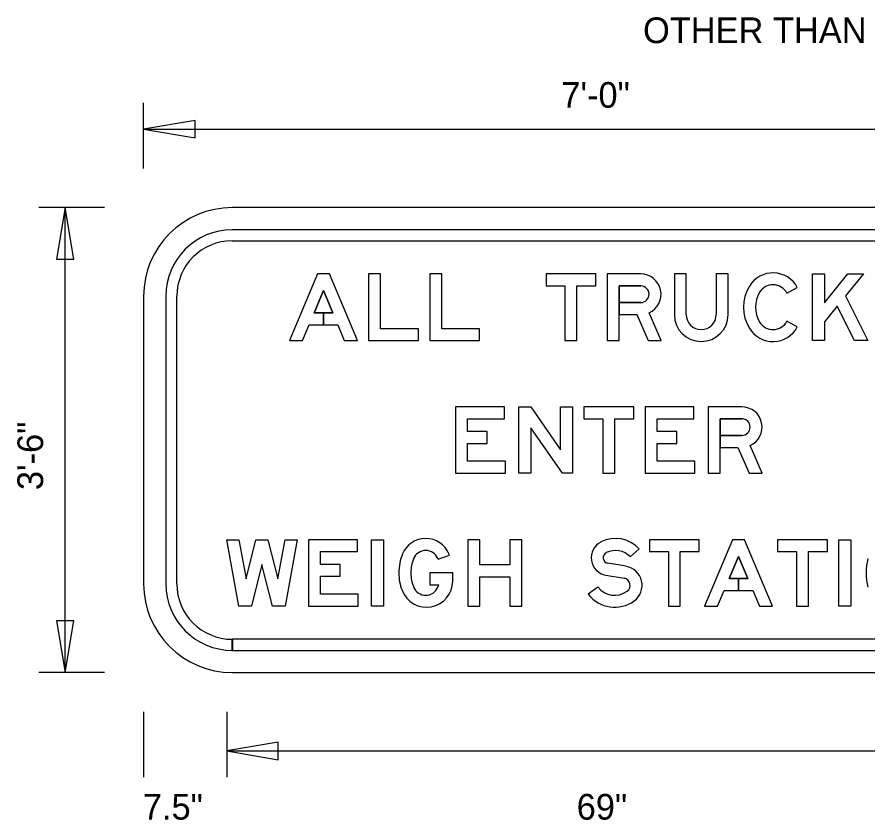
# Model space of a CAD drawing. Extents: x 0 to 770, y 0 to 495.
# Drawn here: x 203.8 to 319.6, y 378.3 to 487.7 of the extents above; entities that cross this region are included whole.
import ezdxf

# ---------------------------------------------------------------- set-up
doc = ezdxf.new("R2010")
doc.units = 0
for name, color, linetype in [('Dimension', 7, 'Continuous'), ('GSBWFill', 7, 'Continuous'), ('GSColorFill', 7, 'Continuous'), ('GSDims', 7, 'Continuous'), ('GSOutline', 7, 'Continuous'), ('TextStructures', 7, 'Continuous')]:
    doc.layers.add(name, color=color, linetype=linetype)

msp = doc.modelspace()

# ---------------------------------------------------------------- linework, layer by layer
at = {"layer": 'Dimension'}
for points in [[(221, 472.41), (228.02, 471.22), (228.02, 473.59)], [(210.32, 461.72), (209.13, 454.7), (211.5, 454.7)], [(210.32, 398.41), (211.5, 405.43), (209.13, 405.43)], [(232.31, 387.73), (239.32, 386.54), (239.32, 388.91)]]:
    msp.add_lwpolyline(points, close=True, dxfattribs=at)
at = {"layer": 'GSBWFill'}
for p, q in [((335.56, 461.72), (233.06, 461.72)), ((335.56, 458.71), (233.06, 458.71)), ((233.06, 457.2), (335.56, 457.2)), ((298.92, 452.68), (298.92, 447.14)), ((308.52, 450.08), (309.95, 450.85)), ((221, 449.66), (221, 410.47)), ((224.01, 449.66), (224.01, 410.47)), ((225.52, 410.47), (225.52, 449.66)), ((309.95, 445.46), (308.52, 446.23)), ((308.52, 446.23), (308.52, 446.23)), ((287.23, 414.15), (288.43, 415.25)), ((261.07, 413.85), (262.61, 414.4)), ((286.65, 412.87), (284.18, 413.29)), ((263.06, 410.86), (263.06, 411.98)), ((283.91, 411.68), (286.38, 411.26)), ((282.8, 410.05), (281.51, 409.06)), ((233.06, 401.42), (233.06, 402.93)), ((335.56, 402.93), (233.07, 402.93)), ((233.07, 402.93), (233.07, 401.42)), ((233.07, 401.42), (335.56, 401.42)), ((233.06, 398.41), (335.56, 398.41))]:
    msp.add_line(p, q, dxfattribs=at)
for points in [[(246.74, 447.39), (245.47, 447.39), (245.47, 445.76), (247.42, 445.76), (248.31, 443.63), (250.08, 443.63), (246.28, 452.68), (244.65, 452.68), (240.85, 443.63), (242.62, 443.63), (243.51, 445.76), (245.47, 445.76), (245.47, 447.39), (244.19, 447.39), (245.47, 450.41)], [(258.4, 443.63), (258.4, 445.21), (253.24, 445.21), (253.24, 452.68), (251.62, 452.68), (251.62, 443.63)], [(266.72, 443.63), (266.72, 445.21), (261.56, 445.21), (261.56, 452.68), (259.94, 452.68), (259.94, 443.63)], [(275.76, 451.05), (278.34, 451.05), (278.34, 443.63), (279.97, 443.63), (279.97, 451.05), (282.55, 451.05), (282.55, 452.68), (275.76, 452.68)], [(318.95, 452.68), (316.53, 449.69), (319.54, 443.63), (317.72, 443.63), (315.4, 448.3), (313.66, 446.16), (313.66, 443.63), (312.03, 443.63), (312.03, 452.68), (313.66, 452.68), (313.66, 448.75), (316.85, 452.68)], [(270.25, 427.17), (265.09, 427.17), (265.09, 429.6), (267.76, 429.6), (267.76, 431.23), (265.09, 431.23), (265.09, 432.96), (270.11, 432.96), (270.11, 434.59), (263.46, 434.59), (263.46, 425.54), (270.25, 425.54)], [(279.38, 434.59), (279.38, 425.54), (277.98, 425.54), (273.68, 431.74), (273.68, 425.54), (272.06, 425.54), (272.06, 434.59), (273.69, 434.59), (277.75, 428.73), (277.75, 434.59)], [(280.92, 432.96), (283.5, 432.96), (283.5, 425.54), (285.13, 425.54), (285.13, 432.96), (287.7, 432.96), (287.7, 434.59), (280.92, 434.59)], [(296.02, 427.17), (290.87, 427.17), (290.87, 429.6), (293.54, 429.6), (293.54, 431.23), (290.87, 431.23), (290.87, 432.96), (295.89, 432.96), (295.89, 434.59), (289.24, 434.59), (289.24, 425.54), (296.02, 425.54)], [(237.1, 413.11), (235.67, 407.45), (233.96, 407.45), (232.31, 416.5), (233.96, 416.5), (234.93, 411.17), (236.27, 416.5), (237.92, 416.5), (239.27, 411.17), (240.24, 416.5), (241.89, 416.5), (240.24, 407.45), (238.52, 407.45)], [(250.21, 409.08), (245.06, 409.08), (245.06, 411.51), (247.73, 411.51), (247.73, 413.14), (245.06, 413.14), (245.06, 414.87), (250.08, 414.87), (250.08, 416.5), (243.43, 416.5), (243.43, 407.45), (250.21, 407.45)], [(252.02, 407.45), (252.02, 416.5), (253.65, 416.5), (253.65, 407.45)], [(270.84, 413.06), (266.77, 413.06), (266.77, 416.5), (265.14, 416.5), (265.14, 407.45), (266.77, 407.45), (266.77, 411.43), (270.84, 411.43), (270.84, 407.45), (272.46, 407.45), (272.46, 416.5), (270.84, 416.5)], [(289.83, 414.87), (292.41, 414.87), (292.41, 407.45), (294.03, 407.45), (294.03, 414.87), (296.61, 414.87), (296.61, 416.5), (289.83, 416.5)], [(303.22, 411.21), (301.95, 411.21), (301.95, 409.58), (303.9, 409.58), (304.8, 407.45), (306.56, 407.45), (302.76, 416.5), (301.13, 416.5), (297.34, 407.45), (299.1, 407.45), (299.99, 409.58), (301.95, 409.58), (301.95, 411.21), (300.68, 411.21), (301.95, 414.23)], [(307.28, 414.87), (309.86, 414.87), (309.86, 407.45), (311.49, 407.45), (311.49, 414.87), (314.07, 414.87), (314.07, 416.5), (307.28, 416.5)], [(315.61, 407.45), (315.61, 416.5), (317.23, 416.5), (317.23, 407.45)]]:
    msp.add_lwpolyline(points, close=True, dxfattribs=at)
for points in [[(288.65, 452.68), (284.09, 452.68), (284.09, 443.63), (285.71, 443.63), (285.71, 451.05), (288.65, 451.05)], [(294.85, 447.14), (294.85, 452.68), (293.22, 452.68), (293.22, 447.14)], [(300.55, 447.14), (300.55, 452.68), (298.92, 452.68)], [(288.65, 448.79), (285.71, 448.79), (285.71, 447.16)], [(285.71, 447.16), (288.11, 447.16), (289.64, 443.63), (291.41, 443.63), (289.78, 447.4)], [(302.4, 434.59), (297.83, 434.59), (297.83, 425.54), (299.46, 425.54), (299.46, 432.96), (302.4, 432.96)], [(302.4, 430.7), (299.46, 430.7), (299.46, 429.07)], [(299.46, 429.07), (301.86, 429.07), (303.39, 425.54), (305.16, 425.54), (303.53, 429.31)], [(263.06, 411.98), (259.94, 411.98), (259.94, 410.35), (261.16, 410.35)]]:
    msp.add_lwpolyline(points, dxfattribs=at)
for centre, radius, start, end in [((233.06, 449.66), 12.06, 90, 180), ((233.06, 449.66), 9.04, 90, 180), ((233.06, 449.66), 7.54, 90, 180), ((296.88, 447.14), 3.66, 180, 0), ((296.88, 447.14), 2.04, 180, 0), ((259.39, 413.25), 3.41, 22.4256, 157.5744), ((284.31, 414.04), 2.4, 116.9123, 260.4087), ((285.21, 412.27), 4.39, 42.8759, 116.9123), ((259.39, 413.25), 1.78, 22.4256, 157.5744), ((284.31, 414.04), 0.769, 116.9123, 260.4087), ((285.21, 412.27), 2.76, 42.8759, 116.9123), ((262.47, 411.98), 6.74, 157.5744, 180), ((262.47, 411.98), 5.11, 157.5744, 180), ((256.32, 411.98), 5.11, 21.4721, 22.4256), ((256.32, 411.98), 6.74, 21.0425, 22.4256), ((286.21, 410.28), 2.62, 306.123, 80.4087), ((262.47, 411.98), 6.74, 180, 200.6303), ((262.47, 411.98), 5.11, 180, 202.4256), ((286.21, 410.28), 0.995, 306.123, 80.4087), ((233.06, 410.47), 12.06, 180, 270), ((233.06, 410.47), 9.04, 180, 270), ((233.06, 410.47), 7.54, 180, 270), ((259.5, 410.86), 3.56, 200.6303, 0), ((259.39, 410.71), 1.78, 202.4256, 337.5744), ((256.32, 411.98), 5.11, 337.5744, 341.4227), ((285.09, 411.82), 2.89, 217.5895, 306.123), ((285.09, 411.82), 4.52, 217.5895, 306.123)]:
    msp.add_arc(centre, radius, start, end, dxfattribs=at)
for centre, major_axis, start_param, end_param in [((306.64, 449.08), (0, 3.75), 5.201543, 7.308565), ((288.65, 449.92), (0, 2.76), 3.562504, 6.283185), ((288.65, 449.92), (0, 1.13), 3.141593, 6.283185), ((308.17, 448.15), (0, 5.54), 1.025379, 2.116213), ((306.64, 449.08), (0, 2.13), 5.201543, 7.308565), ((308.17, 448.15), (0, 3.91), 1.025379, 2.116213), ((306.64, 447.23), (0, 2.13), 2.116213, 4.223235), ((306.64, 447.23), (0, 3.75), 2.116213, 4.223235), ((302.4, 431.83), (0, 2.76), 3.562504, 6.283185), ((302.4, 431.83), (0, 1.13), 3.141593, 6.283185), ((326.91, 411.98), (0, 7.6), 1.309664, 1.831929)]:
    msp.add_ellipse(centre, major_axis=major_axis, ratio=0.999994, start_param=start_param, end_param=end_param, dxfattribs=at)
at = {"layer": 'GSColorFill'}
for p, q in [((298.92, 452.68), (298.92, 447.14)), ((308.52, 450.08), (309.95, 450.85)), ((309.95, 445.46), (308.52, 446.23)), ((308.52, 446.23), (308.52, 446.23)), ((287.23, 414.15), (288.43, 415.25)), ((261.07, 413.85), (262.61, 414.4)), ((286.65, 412.87), (284.18, 413.29)), ((263.06, 410.86), (263.06, 411.98)), ((283.91, 411.68), (286.38, 411.26)), ((282.8, 410.05), (281.51, 409.06))]:
    msp.add_line(p, q, dxfattribs=at)
for points in [[(246.74, 447.39), (245.47, 447.39), (245.47, 445.76), (247.42, 445.76), (248.31, 443.63), (250.08, 443.63), (246.28, 452.68), (244.65, 452.68), (240.85, 443.63), (242.62, 443.63), (243.51, 445.76), (245.47, 445.76), (245.47, 447.39), (244.19, 447.39), (245.47, 450.41)], [(258.4, 443.63), (258.4, 445.21), (253.24, 445.21), (253.24, 452.68), (251.62, 452.68), (251.62, 443.63)], [(266.72, 443.63), (266.72, 445.21), (261.56, 445.21), (261.56, 452.68), (259.94, 452.68), (259.94, 443.63)], [(275.76, 451.05), (278.34, 451.05), (278.34, 443.63), (279.97, 443.63), (279.97, 451.05), (282.55, 451.05), (282.55, 452.68), (275.76, 452.68)], [(318.95, 452.68), (316.53, 449.69), (319.54, 443.63), (317.72, 443.63), (315.4, 448.3), (313.66, 446.16), (313.66, 443.63), (312.03, 443.63), (312.03, 452.68), (313.66, 452.68), (313.66, 448.75), (316.85, 452.68)], [(270.25, 427.17), (265.09, 427.17), (265.09, 429.6), (267.76, 429.6), (267.76, 431.23), (265.09, 431.23), (265.09, 432.96), (270.11, 432.96), (270.11, 434.59), (263.46, 434.59), (263.46, 425.54), (270.25, 425.54)], [(279.38, 434.59), (279.38, 425.54), (277.98, 425.54), (273.68, 431.74), (273.68, 425.54), (272.06, 425.54), (272.06, 434.59), (273.69, 434.59), (277.75, 428.73), (277.75, 434.59)], [(280.92, 432.96), (283.5, 432.96), (283.5, 425.54), (285.13, 425.54), (285.13, 432.96), (287.7, 432.96), (287.7, 434.59), (280.92, 434.59)], [(296.02, 427.17), (290.87, 427.17), (290.87, 429.6), (293.54, 429.6), (293.54, 431.23), (290.87, 431.23), (290.87, 432.96), (295.89, 432.96), (295.89, 434.59), (289.24, 434.59), (289.24, 425.54), (296.02, 425.54)], [(237.1, 413.11), (235.67, 407.45), (233.96, 407.45), (232.31, 416.5), (233.96, 416.5), (234.93, 411.17), (236.27, 416.5), (237.92, 416.5), (239.27, 411.17), (240.24, 416.5), (241.89, 416.5), (240.24, 407.45), (238.52, 407.45)], [(250.21, 409.08), (245.06, 409.08), (245.06, 411.51), (247.73, 411.51), (247.73, 413.14), (245.06, 413.14), (245.06, 414.87), (250.08, 414.87), (250.08, 416.5), (243.43, 416.5), (243.43, 407.45), (250.21, 407.45)], [(252.02, 407.45), (252.02, 416.5), (253.65, 416.5), (253.65, 407.45)], [(270.84, 413.06), (266.77, 413.06), (266.77, 416.5), (265.14, 416.5), (265.14, 407.45), (266.77, 407.45), (266.77, 411.43), (270.84, 411.43), (270.84, 407.45), (272.46, 407.45), (272.46, 416.5), (270.84, 416.5)], [(289.83, 414.87), (292.41, 414.87), (292.41, 407.45), (294.03, 407.45), (294.03, 414.87), (296.61, 414.87), (296.61, 416.5), (289.83, 416.5)], [(303.22, 411.21), (301.95, 411.21), (301.95, 409.58), (303.9, 409.58), (304.8, 407.45), (306.56, 407.45), (302.76, 416.5), (301.13, 416.5), (297.34, 407.45), (299.1, 407.45), (299.99, 409.58), (301.95, 409.58), (301.95, 411.21), (300.68, 411.21), (301.95, 414.23)], [(307.28, 414.87), (309.86, 414.87), (309.86, 407.45), (311.49, 407.45), (311.49, 414.87), (314.07, 414.87), (314.07, 416.5), (307.28, 416.5)], [(315.61, 407.45), (315.61, 416.5), (317.23, 416.5), (317.23, 407.45)]]:
    msp.add_lwpolyline(points, close=True, dxfattribs=at)
for points in [[(288.65, 452.68), (284.09, 452.68), (284.09, 443.63), (285.71, 443.63), (285.71, 451.05), (288.65, 451.05)], [(294.85, 447.14), (294.85, 452.68), (293.22, 452.68), (293.22, 447.14)], [(300.55, 447.14), (300.55, 452.68), (298.92, 452.68)], [(288.65, 448.79), (285.71, 448.79), (285.71, 447.16)], [(285.71, 447.16), (288.11, 447.16), (289.64, 443.63), (291.41, 443.63), (289.78, 447.4)], [(302.4, 434.59), (297.83, 434.59), (297.83, 425.54), (299.46, 425.54), (299.46, 432.96), (302.4, 432.96)], [(302.4, 430.7), (299.46, 430.7), (299.46, 429.07)], [(299.46, 429.07), (301.86, 429.07), (303.39, 425.54), (305.16, 425.54), (303.53, 429.31)], [(263.06, 411.98), (259.94, 411.98), (259.94, 410.35), (261.16, 410.35)]]:
    msp.add_lwpolyline(points, dxfattribs=at)
for centre, radius, start, end in [((296.88, 447.14), 3.66, 180, 0), ((296.88, 447.14), 2.04, 180, 0), ((259.39, 413.25), 3.41, 22.4256, 157.5744), ((284.31, 414.04), 2.4, 116.9123, 260.4087), ((285.21, 412.27), 4.39, 42.8759, 116.9123), ((259.39, 413.25), 1.78, 22.4256, 157.5744), ((284.31, 414.04), 0.769, 116.9123, 260.4087), ((285.21, 412.27), 2.76, 42.8759, 116.9123), ((262.47, 411.98), 6.74, 157.5744, 180), ((262.47, 411.98), 5.11, 157.5744, 180), ((256.32, 411.98), 5.11, 21.4721, 22.4256), ((256.32, 411.98), 6.74, 21.0425, 22.4256), ((286.21, 410.28), 2.62, 306.123, 80.4087), ((262.47, 411.98), 6.74, 180, 200.6303), ((262.47, 411.98), 5.11, 180, 202.4256), ((286.21, 410.28), 0.995, 306.123, 80.4087), ((259.5, 410.86), 3.56, 200.6303, 0), ((259.39, 410.71), 1.78, 202.4256, 337.5744), ((256.32, 411.98), 5.11, 337.5744, 341.4227), ((285.09, 411.82), 2.89, 217.5895, 306.123), ((285.09, 411.82), 4.52, 217.5895, 306.123)]:
    msp.add_arc(centre, radius, start, end, dxfattribs=at)
for centre, major_axis, start_param, end_param in [((306.64, 449.08), (0, 3.75), 5.201543, 7.308565), ((288.65, 449.92), (0, 2.76), 3.562504, 6.283185), ((288.65, 449.92), (0, 1.13), 3.141593, 6.283185), ((308.17, 448.15), (0, 5.54), 1.025379, 2.116213), ((306.64, 449.08), (0, 2.13), 5.201543, 7.308565), ((308.17, 448.15), (0, 3.91), 1.025379, 2.116213), ((306.64, 447.23), (0, 2.13), 2.116213, 4.223235), ((306.64, 447.23), (0, 3.75), 2.116213, 4.223235), ((302.4, 431.83), (0, 2.76), 3.562504, 6.283185), ((302.4, 431.83), (0, 1.13), 3.141593, 6.283185), ((326.91, 411.98), (0, 7.6), 1.309664, 1.831929)]:
    msp.add_ellipse(centre, major_axis=major_axis, ratio=0.999994, start_param=start_param, end_param=end_param, dxfattribs=at)
at = {"layer": 'GSDims'}
for p, q in [((221, 467.06), (221, 475.97)), ((221, 472.41), (347.62, 472.41)), ((215.66, 461.72), (206.75, 461.72)), ((210.32, 398.41), (210.32, 461.72)), ((215.66, 398.41), (206.75, 398.41)), ((221, 393.07), (221, 384.16)), ((232.31, 393.07), (232.31, 384.16)), ((232.31, 393.07), (232.31, 384.16)), ((232.31, 387.73), (336.32, 387.73))]:
    msp.add_line(p, q, dxfattribs=at)
at = {"layer": 'GSOutline'}
for p, q in [((298.92, 452.68), (298.92, 447.14)), ((308.52, 450.08), (309.95, 450.85)), ((285.71, 448.79), (288.65, 448.79)), ((309.95, 445.46), (308.52, 446.23)), ((308.52, 446.23), (308.52, 446.23)), ((299.46, 430.7), (302.4, 430.7)), ((287.23, 414.15), (288.43, 415.25)), ((261.07, 413.85), (262.61, 414.4)), ((286.65, 412.87), (284.18, 413.29)), ((263.06, 410.86), (263.06, 411.98)), ((283.91, 411.68), (286.38, 411.26)), ((282.8, 410.05), (281.51, 409.06))]:
    msp.add_line(p, q, dxfattribs=at)
for points in [[(243.51, 445.76), (247.42, 445.76), (248.31, 443.63), (250.08, 443.63), (246.28, 452.68), (244.65, 452.68), (240.85, 443.63), (242.62, 443.63)], [(258.4, 443.63), (258.4, 445.21), (253.24, 445.21), (253.24, 452.68), (251.62, 452.68), (251.62, 443.63)], [(266.72, 443.63), (266.72, 445.21), (261.56, 445.21), (261.56, 452.68), (259.94, 452.68), (259.94, 443.63)], [(275.76, 451.05), (278.34, 451.05), (278.34, 443.63), (279.97, 443.63), (279.97, 451.05), (282.55, 451.05), (282.55, 452.68), (275.76, 452.68)], [(318.95, 452.68), (316.53, 449.69), (319.54, 443.63), (317.72, 443.63), (315.4, 448.3), (313.66, 446.16), (313.66, 443.63), (312.03, 443.63), (312.03, 452.68), (313.66, 452.68), (313.66, 448.75), (316.85, 452.68)], [(246.74, 447.39), (245.47, 450.41), (244.19, 447.39)], [(270.25, 427.17), (265.09, 427.17), (265.09, 429.6), (267.76, 429.6), (267.76, 431.23), (265.09, 431.23), (265.09, 432.96), (270.11, 432.96), (270.11, 434.59), (263.46, 434.59), (263.46, 425.54), (270.25, 425.54)], [(279.38, 434.59), (279.38, 425.54), (277.98, 425.54), (273.68, 431.74), (273.68, 425.54), (272.06, 425.54), (272.06, 434.59), (273.69, 434.59), (277.75, 428.73), (277.75, 434.59)], [(280.92, 432.96), (283.5, 432.96), (283.5, 425.54), (285.13, 425.54), (285.13, 432.96), (287.7, 432.96), (287.7, 434.59), (280.92, 434.59)], [(296.02, 427.17), (290.87, 427.17), (290.87, 429.6), (293.54, 429.6), (293.54, 431.23), (290.87, 431.23), (290.87, 432.96), (295.89, 432.96), (295.89, 434.59), (289.24, 434.59), (289.24, 425.54), (296.02, 425.54)], [(237.1, 413.11), (235.67, 407.45), (233.96, 407.45), (232.31, 416.5), (233.96, 416.5), (234.93, 411.17), (236.27, 416.5), (237.92, 416.5), (239.27, 411.17), (240.24, 416.5), (241.89, 416.5), (240.24, 407.45), (238.52, 407.45)], [(250.21, 409.08), (245.06, 409.08), (245.06, 411.51), (247.73, 411.51), (247.73, 413.14), (245.06, 413.14), (245.06, 414.87), (250.08, 414.87), (250.08, 416.5), (243.43, 416.5), (243.43, 407.45), (250.21, 407.45)], [(252.02, 407.45), (252.02, 416.5), (253.65, 416.5), (253.65, 407.45)], [(270.84, 413.06), (266.77, 413.06), (266.77, 416.5), (265.14, 416.5), (265.14, 407.45), (266.77, 407.45), (266.77, 411.43), (270.84, 411.43), (270.84, 407.45), (272.46, 407.45), (272.46, 416.5), (270.84, 416.5)], [(289.83, 414.87), (292.41, 414.87), (292.41, 407.45), (294.03, 407.45), (294.03, 414.87), (296.61, 414.87), (296.61, 416.5), (289.83, 416.5)], [(299.99, 409.58), (303.9, 409.58), (304.8, 407.45), (306.56, 407.45), (302.76, 416.5), (301.13, 416.5), (297.34, 407.45), (299.1, 407.45)], [(307.28, 414.87), (309.86, 414.87), (309.86, 407.45), (311.49, 407.45), (311.49, 414.87), (314.07, 414.87), (314.07, 416.5), (307.28, 416.5)], [(315.61, 407.45), (315.61, 416.5), (317.23, 416.5), (317.23, 407.45)], [(303.22, 411.21), (301.95, 414.23), (300.68, 411.21)]]:
    msp.add_lwpolyline(points, close=True, dxfattribs=at)
for points in [[(288.65, 452.68), (284.09, 452.68), (284.09, 443.63), (285.71, 443.63), (285.71, 447.16), (288.11, 447.16)], [(294.85, 447.14), (294.85, 452.68), (293.22, 452.68), (293.22, 447.14)], [(300.55, 447.14), (300.55, 452.68), (298.92, 452.68)], [(288.65, 451.05), (285.71, 451.05), (285.71, 448.79)], [(288.11, 447.16), (289.64, 443.63), (291.41, 443.63), (289.78, 447.4)], [(302.4, 434.59), (297.83, 434.59), (297.83, 425.54), (299.46, 425.54), (299.46, 429.07), (301.86, 429.07)], [(302.4, 432.96), (299.46, 432.96), (299.46, 430.7)], [(301.86, 429.07), (303.39, 425.54), (305.16, 425.54), (303.53, 429.31)], [(263.06, 411.98), (259.94, 411.98), (259.94, 410.35), (261.16, 410.35)]]:
    msp.add_lwpolyline(points, dxfattribs=at)
for centre, radius, start, end in [((296.88, 447.14), 3.66, 180, 0), ((296.88, 447.14), 2.04, 180, 0), ((259.39, 413.25), 3.41, 22.4256, 157.5744), ((284.31, 414.04), 2.4, 116.9123, 260.4087), ((285.21, 412.27), 4.39, 42.8759, 116.9123), ((259.39, 413.25), 1.78, 22.4256, 157.5744), ((284.31, 414.04), 0.769, 116.9123, 260.4087), ((285.21, 412.27), 2.76, 42.8759, 116.9123), ((262.47, 411.98), 6.74, 157.5744, 180), ((262.47, 411.98), 5.11, 157.5744, 180), ((256.32, 411.98), 5.11, 21.4721, 22.4256), ((256.32, 411.98), 6.74, 21.0425, 22.4256), ((286.21, 410.28), 2.62, 306.123, 80.4087), ((262.47, 411.98), 6.74, 180, 200.6303), ((262.47, 411.98), 5.11, 180, 202.4256), ((286.21, 410.28), 0.995, 306.123, 80.4087), ((259.5, 410.86), 3.56, 200.6303, 0), ((259.39, 410.71), 1.78, 202.4256, 337.5744), ((256.32, 411.98), 5.11, 337.5744, 341.4227), ((285.09, 411.82), 2.89, 217.5895, 306.123), ((285.09, 411.82), 4.52, 217.5895, 306.123)]:
    msp.add_arc(centre, radius, start, end, dxfattribs=at)
for centre, major_axis, start_param, end_param in [((306.64, 449.08), (0, 3.75), 5.201543, 7.308565), ((288.65, 449.92), (0, 2.76), 3.562504, 6.283185), ((288.65, 449.92), (0, 1.13), 3.141593, 6.283185), ((308.17, 448.15), (0, 5.54), 1.025379, 2.116213), ((306.64, 449.08), (0, 2.13), 5.201543, 7.308565), ((308.17, 448.15), (0, 3.91), 1.025379, 2.116213), ((306.64, 447.23), (0, 2.13), 2.116213, 4.223235), ((306.64, 447.23), (0, 3.75), 2.116213, 4.223235), ((302.4, 431.83), (0, 2.76), 3.562504, 6.283185), ((302.4, 431.83), (0, 1.13), 3.141593, 6.283185), ((326.91, 411.98), (0, 7.6), 1.309664, 1.831929)]:
    msp.add_ellipse(centre, major_axis=major_axis, ratio=0.999994, start_param=start_param, end_param=end_param, dxfattribs=at)

# ---------------------------------------------------------------- texts
at = {"layer": 'TextStructures'}
for s, p in [('OTHER THAN FREEWAY USE', (288.96, 484.11)), ('7\'-0"', (277.84, 475.3)), ('7.5"', (220.89, 378.38)), ('69"', (279.93, 378.38))]:
    msp.add_text(s, height=3.5, dxfattribs=at).set_placement(p)
msp.add_text('3\'-6"', height=3.5, rotation=90, dxfattribs=at).set_placement((207.32, 423.25))

doc.saveas('drawing.dxf')
